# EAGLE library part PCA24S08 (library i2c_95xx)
1024 x 8-Bit CMOS EEPROM with Access Protection
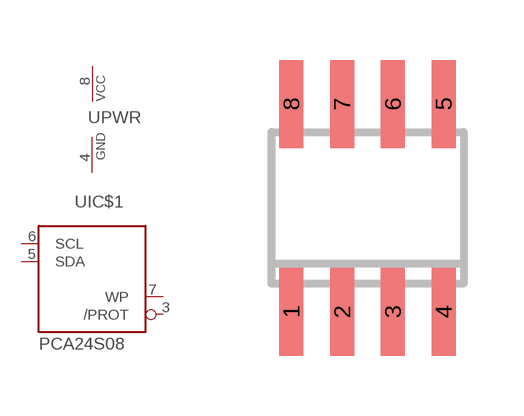
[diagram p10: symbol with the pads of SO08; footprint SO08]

Designator prefix -; gates IC$1=PCA24S08 PWR=PWRN

## PCA24S08  [SO08]
3  IC$1:/PROT  in
4  PWR:GND  pwr
5  IC$1:SDA
6  IC$1:SCL  in
7  IC$1:WP  in
8  PWR:VCC  pwr

## Footprint SO08 (pad centres in mm)
smd 0.6 x 2.2: 1 -1.905,-2.6; 2 -0.635,-2.6; 3 0.635,-2.6; 4 1.905,-2.6; 5 1.905,2.6; 6 0.635,2.6; 7 -0.635,2.6; 8 -1.905,2.6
